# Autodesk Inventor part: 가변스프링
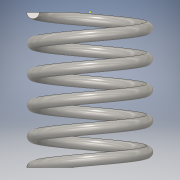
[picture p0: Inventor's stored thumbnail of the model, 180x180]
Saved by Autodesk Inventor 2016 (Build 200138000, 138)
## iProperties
Created: 2017-12
Part Number: 가변스프링
Material: 스테인레스 스틸
Document SubType Name: Modeling
Designer: 605-06
Density: 8 g/cm^3
Appearance: 반연마
Mass: 6.98322 g
Surface Area: 17.73 cm^2
Volume: 0.872902 cm^3
Author: 605-06
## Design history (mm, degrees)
sketch "스케치1"
  geometry: L1 (0, 0)-(24.5, 0); L2 (24.5, 0)-(24.5, -9); L3 (24.5, -9)-(0, -9); L4 (0, -9)-(0, 0); C1 r 1 at (0, -9)
  constraints: 8 end point, 2 parallel, 1 centre point, 1 coincident, 1 horizontal, 1 perpendicular
  dimensions: "d0" = 18 diameter of L3 L1; "d1" = 24.5 distance between parallel lines of L4 L2 (derived); "d2" = 2 diameter of C1
feature "코일1" sketch "스케치1" pitch "d3" = 10; turns "d5" = 5; dims "d4" = 24.5 (= d1), "d6" = 0, angle "d7" = 90 deg, angle "d8" = 90 deg, "d9" = 0, "d10" = 0
sketch "스케치2"
  geometry: L1 (0, -10)-(0, -8) reference; 1 further point
  constraints: 1 vertical alignment
extrude "돌출1" cut sketch "스케치2" stored distance "d11" = 10; taper "d12" = 0 deg
node "작업 평면1"
sketch "스케치3"
  geometry: 1 further point
sketch "스케치4"
  geometry: L1 (10, 0)-(8, 0) reference; 2 further points
  constraints: 2 other
extrude "돌출2" cut sketch "스케치4" stored distance "d14" = 10; taper "d15" = 0 deg
node "솔리드1"
node "절단 모서리 투영1"
node "절단 모서리 투영2"
other parameters: "d13" = 90 deg
